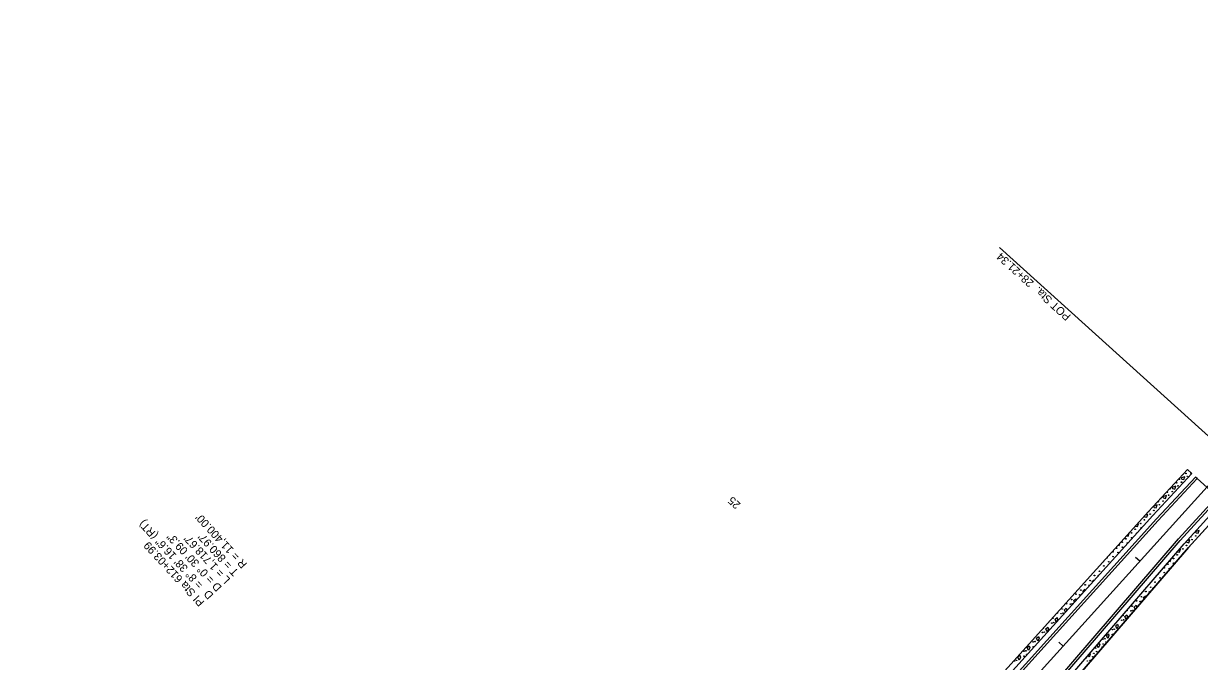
# Model space of a CAD drawing. Extents: x 1262642 to 1268358, y 767825 to 773481.
# Drawn here: x 1266385 to 1267414, y 772720 to 773278 of the extents above; entities that cross this region are included whole.
import ezdxf

# ---------------------------------------------------------------- set-up
doc = ezdxf.new("R2010")
doc.units = 0
for name, color, linetype in [('Prop Conc 2ft 6in Curb and Gutter', 7, 'Continuous'), ('Prop Conc 4in Sidewalk', 7, 'Continuous'), ('Prop EOT', 7, 'Continuous'), ('Prop Horizontal Alignment', 7, 'Continuous'), ('Prop Horizontal Alignment Curve and Spiral Data', 7, 'Continuous'), ('Prop Horizontal Alignment Station Label', 7, 'Continuous'), ('Prop Horizontal Alignment Tick Label', 7, 'Continuous'), ('Prop Horizontal Alignment Tick Small', 7, 'Continuous'), ('Prop Lane Lines', 7, 'Continuous'), ('Prop Paved Shoulder', 7, 'Continuous'), ('Prop Shade Light', 7, 'Continuous')]:
    doc.layers.add(name, color=color, linetype=linetype)

msp = doc.modelspace()

# ---------------------------------------------------------------- linework, layer by layer
at = {"layer": 'Prop Conc 2ft 6in Curb and Gutter'}
for p, q in [((1267369.3, 772851.1), (1267403.4, 772887.8)), ((1267407.1, 772884.4), (1267403.4, 772887.8)), ((1267373, 772847.7), (1267407.1, 772884.4)), ((1267376.3, 772844.7), (1267410.4, 772881.3)), ((1267401.2, 772881.6), (1267397.9, 772880.5)), ((1267397.9, 772880.5), (1267398.5, 772879.5)), ((1267398.5, 772879.5), (1267400.3, 772879.1)), ((1267400.3, 772879.1), (1267401.2, 772881.6)), ((1267411.8, 772880), (1267410.4, 772881.3)), ((1267393.1, 772873.3), (1267389.8, 772872.2)), ((1267389.8, 772872.2), (1267390.4, 772871.2)), ((1267390.4, 772871.2), (1267392.2, 772870.8)), ((1267392.2, 772870.8), (1267393.1, 772873.3)), ((1267376.9, 772856.9), (1267373.7, 772855.8)), ((1267376, 772854.4), (1267376.9, 772856.9)), ((1267385, 772865.1), (1267381.6, 772864)), ((1267381.6, 772864), (1267382.3, 772863)), ((1267382.3, 772863), (1267384.1, 772862.6)), ((1267384.1, 772862.6), (1267385, 772865.1)), ((1267430.7, 772862.9), (1267397.1, 772825.9)), ((1267400.5, 772822.9), (1267434, 772859.9)), ((1267437.7, 772856.5), (1267404.2, 772819.6)), ((1267207.9, 772672.4), (1267369.3, 772851.1)), ((1267211.4, 772668.8), (1267373, 772847.7)), ((1267365.7, 772847.1), (1267366, 772846.5)), ((1267366, 772846.5), (1267367.8, 772846.1)), ((1267368.8, 772848.6), (1267366.3, 772847.8)), ((1267367.8, 772846.1), (1267368.8, 772848.6)), ((1267373.6, 772855.7), (1267374.2, 772854.7)), ((1267374.2, 772854.7), (1267376, 772854.4)), ((1267214.6, 772665.6), (1267376.3, 772844.7)), ((1267357.8, 772838.4), (1267357.9, 772838.2)), ((1267357.9, 772838.2), (1267359.7, 772837.9)), ((1267360.6, 772840.4), (1267359.2, 772839.9)), ((1267359.7, 772837.9), (1267360.6, 772840.4)), ((1267174.2, 772567.2), (1267397.1, 772825.9)), ((1267350.2, 772829.9), (1267351.6, 772829.6)), ((1267351.6, 772829.6), (1267352.5, 772832.1)), ((1267352.5, 772832.1), (1267352, 772832)), ((1267402.3, 772824.9), (1267402.8, 772824.2)), ((1267405.5, 772826.3), (1267402.7, 772825.4)), ((1267404.6, 772823.8), (1267405.5, 772826.3)), ((1267413.6, 772834.6), (1267410.2, 772833.4)), ((1267410.2, 772833.4), (1267410.9, 772832.5)), ((1267410.9, 772832.5), (1267412.7, 772832.1)), ((1267412.7, 772832.1), (1267413.6, 772834.6)), ((1267177.5, 772564.2), (1267400.5, 772822.9)), ((1267404.2, 772819.6), (1267181.3, 772560.9)), ((1267342.6, 772821.6), (1267343.5, 772821.4)), ((1267343.5, 772821.4), (1267344.2, 772823.2)), ((1267394.6, 772816.1), (1267394.6, 772816)), ((1267394.6, 772816), (1267396.4, 772815.6)), ((1267397.4, 772818.1), (1267395.9, 772817.6)), ((1267396.4, 772815.6), (1267397.4, 772818.1)), ((1267402.8, 772824.2), (1267404.6, 772823.8)), ((1267335.1, 772813.2), (1267335.3, 772813.1)), ((1267335.3, 772813.1), (1267335.6, 772813.7)), ((1267387.2, 772807.6), (1267388.3, 772807.3)), ((1267388.3, 772807.3), (1267389.2, 772809.8)), ((1267389.2, 772809.8), (1267389.2, 772809.8)), ((1267380, 772799.1), (1267380.2, 772799.1)), ((1267380.2, 772799.1), (1267380.4, 772799.6)), ((1267320.1, 772789.9), (1267321.8, 772791.3)), ((1267320.3, 772789.4), (1267320.1, 772789.9)), ((1267321.8, 772791.3), (1267321.9, 772791.1)), ((1267373.1, 772784.1), (1267374.8, 772785.6)), ((1267373.2, 772783.7), (1267373.1, 772784.1)), ((1267374.8, 772785.6), (1267374.8, 772785.5)), ((1267303.9, 772773.4), (1267305.6, 772774.9)), ((1267305.6, 772774.9), (1267306, 772773.6)), ((1267312, 772781.6), (1267313.7, 772783.1)), ((1267312.4, 772780.6), (1267312, 772781.6)), ((1267313.7, 772783.1), (1267313.9, 772782.3)), ((1267365, 772775.8), (1267366.6, 772777.3)), ((1267365.4, 772774.6), (1267365, 772775.8)), ((1267366.6, 772777.3), (1267367, 772776.4)), ((1267295.8, 772765.1), (1267297.4, 772766.6)), ((1267296.6, 772763.1), (1267295.8, 772765.1)), ((1267297.4, 772766.6), (1267298, 772765.1)), ((1267298, 772765.1), (1267297.6, 772764.3)), ((1267304.5, 772771.9), (1267303.9, 772773.4)), ((1267356.8, 772767.6), (1267358.5, 772769.1)), ((1267357.6, 772765.6), (1267356.8, 772767.6)), ((1267358.5, 772769.1), (1267359.1, 772767.5)), ((1267359.1, 772767.5), (1267358.8, 772766.9)), ((1267287.6, 772756.9), (1267289.3, 772758.4)), ((1267288.6, 772754.3), (1267287.6, 772756.9)), ((1267289.8, 772756.8), (1267288.9, 772754.6)), ((1267289.3, 772758.4), (1267289.8, 772756.8)), ((1267348.7, 772759.3), (1267350.4, 772760.8)), ((1267349.8, 772756.6), (1267348.7, 772759.3)), ((1267350.9, 772759.3), (1267349.8, 772756.6)), ((1267350.4, 772760.8), (1267350.9, 772759.3)), ((1267279.5, 772748.6), (1267281.2, 772750.1)), ((1267280.6, 772746), (1267279.5, 772748.6)), ((1267281.7, 772748.6), (1267280.6, 772746)), ((1267281.2, 772750.1), (1267281.7, 772748.6)), ((1267332.5, 772742.8), (1267334.2, 772744.3)), ((1267333.6, 772740.2), (1267332.5, 772742.8)), ((1267334.7, 772742.8), (1267333.6, 772740.2)), ((1267334.2, 772744.3), (1267334.7, 772742.8)), ((1267340.6, 772751.1), (1267342.3, 772752.6)), ((1267341.7, 772748.4), (1267340.6, 772751.1)), ((1267342.8, 772751), (1267341.7, 772748.4)), ((1267342.3, 772752.6), (1267342.8, 772751)), ((1267263.3, 772732.1), (1267264.9, 772733.6)), ((1267264.9, 772733.6), (1267265.5, 772732.1)), ((1267271.4, 772740.4), (1267273.1, 772741.9)), ((1267272.5, 772737.7), (1267271.4, 772740.4)), ((1267273.6, 772740.3), (1267272.5, 772737.7)), ((1267273.1, 772741.9), (1267273.6, 772740.3)), ((1267324.3, 772734.6), (1267326, 772736.1)), ((1267325.4, 772731.9), (1267324.3, 772734.6)), ((1267326.6, 772734.6), (1267325.4, 772731.9)), ((1267326, 772736.1), (1267326.6, 772734.6)), ((1267255.1, 772723.9), (1267256.8, 772725.4)), ((1267256.2, 772721.2), (1267255.1, 772723.9)), ((1267257.3, 772723.9), (1267256.2, 772721.2)), ((1267256.8, 772725.4), (1267257.3, 772723.9)), ((1267264.3, 772729.5), (1267263.3, 772732.1)), ((1267265.5, 772732.1), (1267264.3, 772729.5)), ((1267317.3, 772723.7), (1267316.5, 772725.5)), ((1267318.4, 772726.3), (1267317.3, 772723.7)), ((1267318.1, 772727.3), (1267318.4, 772726.3)), ((1267323.2, 772725.6), (1267322.1, 772725.3)), ((1267322.1, 772725.3), (1267322.5, 772724.8))]:
    msp.add_line(p, q, dxfattribs=at)
for centre, radius in [((1267393.9, 772876.2), 0.268), ((1267396.3, 772879.3), 0.268), ((1267398.2, 772876.8), 0.292), ((1267402.1, 772884.4), 0.268), ((1267403.2, 772881.9), 0.285), ((1267385.8, 772867.9), 0.268), ((1267390.1, 772868.5), 0.292), ((1267395, 772873.6), 0.285), ((1267377.7, 772859.7), 0.268), ((1267378.8, 772857.1), 0.285), ((1267382, 772860.3), 0.292), ((1267386.9, 772865.4), 0.285), ((1267370.7, 772848.9), 0.285), ((1267373.9, 772852.1), 0.292), ((1267357.6, 772835.6), 0.292), ((1267362.5, 772840.6), 0.285), ((1267365.7, 772843.8), 0.292), ((1267349.5, 772827.3), 0.292), ((1267354.4, 772832.4), 0.285), ((1267354.5, 772828.2), 0.289), ((1267407.4, 772826.6), 0.285), ((1267410.6, 772829.8), 0.292), ((1267338.2, 772815.9), 0.285), ((1267341.4, 772819.1), 0.292), ((1267342.6, 772815.4), 0.268), ((1267346.3, 772824.2), 0.285), ((1267346.4, 772820), 0.289), ((1267350.8, 772823.7), 0.268), ((1267399.3, 772818.4), 0.285), ((1267402.5, 772821.5), 0.292), ((1267334.5, 772807.2), 0.268), ((1267338.3, 772811.7), 0.289), ((1267386.2, 772805), 0.292), ((1267391.1, 772810.1), 0.285), ((1267391.2, 772805.9), 0.289), ((1267394.3, 772813.3), 0.292), ((1267322, 772795.2), 0.289), ((1267326.4, 772798.9), 0.268), ((1267330.2, 772803.5), 0.289), ((1267383, 772801.9), 0.285), ((1267383.1, 772797.7), 0.289), ((1267387.5, 772801.4), 0.268), ((1267313.9, 772787), 0.289), ((1267317.2, 772786.6), 0.268), ((1267318.3, 772790.7), 0.268), ((1267371.2, 772784.9), 0.268), ((1267375, 772789.4), 0.289), ((1267379.3, 772793.1), 0.268), ((1267302, 772774.2), 0.268), ((1267305.8, 772778.8), 0.289), ((1267309.1, 772778.3), 0.268), ((1267310.1, 772782.4), 0.268), ((1267363.1, 772776.6), 0.268), ((1267366.9, 772781.2), 0.289), ((1267370.1, 772780.8), 0.268), ((1267293.9, 772765.9), 0.268), ((1267297.7, 772770.5), 0.289), ((1267300.9, 772770.1), 0.268), ((1267302.6, 772770.5), 0.268), ((1267353.9, 772764.3), 0.268), ((1267355, 772768.4), 0.268), ((1267355.6, 772764.7), 0.268), ((1267358.8, 772773), 0.289), ((1267362, 772772.5), 0.268), ((1267284.7, 772753.6), 0.268), ((1267285.8, 772757.7), 0.268), ((1267286.4, 772754), 0.268), ((1267289.5, 772762.3), 0.289), ((1267292.8, 772761.8), 0.268), ((1267294.5, 772762.2), 0.268), ((1267345.8, 772756), 0.268), ((1267346.9, 772760.2), 0.268), ((1267347.5, 772756.4), 0.268), ((1267276.6, 772745.4), 0.268), ((1267278.2, 772745.7), 0.268), ((1267337.7, 772747.8), 0.268), ((1267337.7, 772743.6), 0.268), ((1267339.3, 772748.2), 0.268), ((1267268.4, 772737.1), 0.268), ((1267268.5, 772732.9), 0.268), ((1267270.1, 772737.5), 0.268), ((1267329.5, 772739.6), 0.268), ((1267329.6, 772735.3), 0.268), ((1267331.2, 772739.9), 0.268), ((1267332, 772737), 0.18), ((1267260.3, 772728.9), 0.268), ((1267260.4, 772724.6), 0.268), ((1267262, 772729.3), 0.268), ((1267262.8, 772726.3), 0.18), ((1267320.6, 772724.1), 0.268), ((1267321.5, 772727.1), 0.268), ((1267323.1, 772731.7), 0.268), ((1267323.9, 772728.7), 0.18), ((1267252.2, 772720.6), 0.268), ((1267253.9, 772721), 0.268), ((1267315.8, 772720.5), 0.18), ((1267318.2, 772721), 0.268)]:
    msp.add_circle(centre, radius, dxfattribs=at)
for centre, radius, start, end in [((1267399.6, 772883.9), 0.18, 283.9915, 350.183), ((1267406.3, 772885), 0.292, 132.6648, 321.5098), ((1267388.2, 772871.1), 0.268, 173.4184, 100.7562), ((1267380.1, 772862.8), 0.268, 253.5603, 20.6142), ((1267369.6, 772851.4), 0.268, 234.1633, 40.0113), ((1267362.7, 772836.5), 0.289, 20.0632, 255.7444), ((1267358.9, 772831.9), 0.268, 73.9755, 201.8322), ((1267406.3, 772829.1), 0.268, 198.7406, 76.7213), ((1267408.7, 772832.3), 0.268, 295.2597, 340.2023), ((1267330, 772807.7), 0.285, 233.6083, 42.1993), ((1267333.2, 772810.8), 0.292, 178.5449, 97.2627), ((1267395.6, 772809.6), 0.268, 47.4451, 231.0471), ((1267399.4, 772814.2), 0.289, 24.1077, 254.3846), ((1267325.3, 772794.8), 0.268, 63.2379, 212.5697), ((1267325.1, 772802.6), 0.292, 301.269, 334.5387), ((1267378.1, 772796.8), 0.292, 209.3866, 69.105), ((1267374.9, 772793.6), 0.285, 293.0954, 345.3962), ((1267310.7, 772778.7), 0.268, 59.222, 216.5856), ((1267350.6, 772764.7), 0.289, 170.0629, 108.4288), ((1267363.7, 772772.9), 0.268, 357.4098, 281.0825), ((1267281.4, 772754), 0.289, 257.5615, 18.2461), ((1267277.6, 772749.5), 0.268, 203.7273, 72.0803), ((1267340.1, 772745.2), 0.18, 55.2261, 223.2661), ((1267345.9, 772751.8), 0.268, 63.1757, 215.3166), ((1267270.9, 772734.5), 0.18, 95.3134, 180.4942), ((1267276.7, 772741.1), 0.268, 42.3811, 233.4266), ((1267328.7, 772732.4), 0.268, 332.3662, 306.1261), ((1267315, 772723.5), 0.268, 192.5685, 85.9232), ((1267321.4, 772731.3), 0.268, 247.5405, 30.9512), ((1267326.3, 772729.2), 0.268, 51.8388, 226.6534), ((1267259.5, 772721.7), 0.268, 119.9078, 155.8999)]:
    msp.add_arc(centre, radius, start, end, dxfattribs=at)
at = {"layer": 'Prop Conc 4in Sidewalk'}
for p, q in [((1267369.3, 772851.1), (1267403.4, 772887.8)), ((1267407.1, 772884.4), (1267403.4, 772887.8)), ((1267373, 772847.7), (1267407.1, 772884.4)), ((1267434, 772859.9), (1267400.5, 772822.9)), ((1267437.7, 772856.5), (1267404.1, 772819.5)), ((1267207.9, 772672.4), (1267369.3, 772851.1)), ((1267211.4, 772668.8), (1267373, 772847.7)), ((1267177.5, 772564.2), (1267400.5, 772822.9)), ((1267181.2, 772560.8), (1267404.3, 772819.7))]:
    msp.add_line(p, q, dxfattribs=at)
at = {"layer": 'Prop EOT'}
for p, q in [((1267377.8, 772843.3), (1267411.8, 772880)), ((1267411.8, 772880), (1267429.2, 772864.2)), ((1267429.2, 772864.2), (1267395.6, 772827.2)), ((1267216, 772664.2), (1267377.8, 772843.3)), ((1267172.7, 772568.5), (1267395.6, 772827.2))]:
    msp.add_line(p, q, dxfattribs=at)
msp.add_arc((1275047.3, 780021.2), 11361, 216.76636, 222.71603, dxfattribs=at)
at = {"layer": 'Prop Horizontal Alignment'}
msp.add_line((1266770.9, 772153.7), (1267443, 772897.7), dxfattribs=at)
msp.add_arc((1275047.3, 780021.2), 11400, 216.76636, 222.99359, dxfattribs=at)
at = {"layer": 'Prop Horizontal Alignment Station Label'}
msp.add_line((1267441.9, 772898.7), (1267239, 773082), dxfattribs=at)
at = {"layer": 'Prop Horizontal Alignment Tick Small'}
for p, q in [((1267361.7, 772807.6), (1267358, 772811)), ((1267294.7, 772733.4), (1267291, 772736.8))]:
    msp.add_line(p, q, dxfattribs=at)
at = {"layer": 'Prop Lane Lines'}
for radius, start, end in [(11373, 216.36494, 223.13275), (11427, 216.3675, 223.54768)]:
    msp.add_arc((1275047.3, 780021.2), radius, start, end, dxfattribs=at)
at = {"layer": 'Prop Paved Shoulder'}
msp.add_arc((1275047.3, 780021.2), 11351, 216.76636, 222.71603, dxfattribs=at)
at = {"layer": 'Prop Shade Light'}
for radius, start in [(11351, 216.76576), (11361, 216.76589)]:
    msp.add_arc((1275047.3, 780021.2), radius, start, 222.71603, dxfattribs=at)

# ---------------------------------------------------------------- texts
at = {"layer": 'Prop Horizontal Alignment Curve and Spiral Data'}
for s, p in [("R = 11,400.00'", (1266581.4, 772805.4)), ('= 8%%d 38\' 16.6" (RT)', (1266543, 772787.6)), ('D = 0%%d 30\' 09.3"', (1266559.3, 772785.1)), ("L = 1,718.67'", (1266566.7, 772791.9)), ("T = 860.97'", (1266574, 772798.7)), ('PI Sta 612+03.99', (1266544.1, 772772.1)), ('D', (1266552, 772778.3))]:
    msp.add_text(s, height=7, rotation=132.6469, dxfattribs=at).set_placement(p)
at = {"layer": 'Prop Horizontal Alignment Station Label'}
msp.add_text('POT Sta.  28+21.34', height=7, rotation=137.9038, dxfattribs=at).set_placement((1267301.9, 773022.5))
at = {"layer": 'Prop Horizontal Alignment Tick Label'}
msp.add_text('25', height=7, rotation=137.9038, dxfattribs=at).set_placement((1267013.1, 772857.8))

doc.saveas('drawing.dxf')
